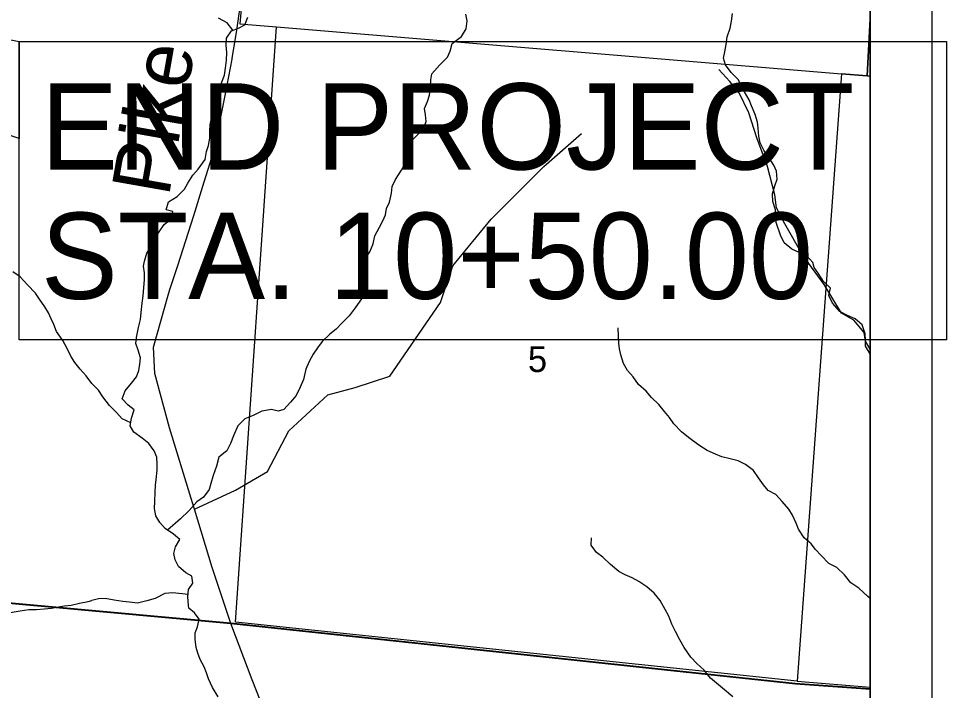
# Model space of a CAD drawing. Extents: x -13.1 to 43.1, y 0 to 22.
# Drawn here: x 7.517 to 9.024, y 15.746 to 16.837 of the extents above; entities that cross this region are included whole.
import ezdxf

# ---------------------------------------------------------------- set-up
doc = ezdxf.new("R2010")
doc.units = 0
for name, color, linetype in [('GM_X_Corporation', 7, 'Continuous'), ('GM_X_Minor_River', 7, 'Continuous'), ('GM_X_Minor_River_Text', 7, 'Continuous'), ('GM_X_Section_Text', 7, 'Continuous'), ('GM_X_State_Route', 7, 'Continuous'), ('GM_X_Township_Road', 7, 'Continuous'), ('SH_Data', 7, 'Continuous'), ('SH_Masking', 7, 'Continuous'), ('SH_Text', 7, 'Continuous')]:
    doc.layers.add(name, color=color, linetype=linetype)

msp = doc.modelspace()

# ---------------------------------------------------------------- linework, layer by layer
at = {"layer": 'GM_X_Corporation'}
for points in [[(8.9, 15.7487), (8.9, 20.9), (7.0804, 20.9), (7.0615, 20.6138), (7.0162, 19.896), (7.0106, 19.8452), (6.9616, 19.1692), (6.9507, 19.0184), (6.8365, 17.1257), (6.8234, 16.908), (6.7528, 15.9566), (7.8612, 15.855), (8.7782, 15.7572)], [(8.9, 15.7487), (8.9, 20.9), (7.0804, 20.9), (7.0615, 20.6138), (7.0162, 19.896), (7.0106, 19.8452), (6.9616, 19.1692), (6.9507, 19.0184), (6.8365, 17.1257), (6.8234, 16.908), (6.7528, 15.9566), (7.8612, 15.855), (8.7782, 15.7572)], [(8.9, 15.7481), (8.9, 20.9), (7.0807, 20.9), (7.0617, 20.6133), (7.0164, 19.8954), (7.0108, 19.8446), (6.9509, 19.0179), (6.8236, 16.9075), (6.7531, 15.956), (7.8614, 15.8545), (8.7784, 15.7567)], [(8.9, 16.8362), (8.9, 17.7183), (7.9639, 17.8036), (7.8759, 16.828), (7.9357, 16.8233), (8.8534, 16.7472), (8.8951, 16.7437)], [(8.9, 16.7433), (8.9, 16.8362), (8.8951, 16.7437)], [(7.9357, 16.8233), (8.8534, 16.7472), (8.7815, 15.7611), (7.8691, 15.8567)], [(8.9, 15.7513), (8.9, 16.7433), (8.8951, 16.7437), (8.8534, 16.7472), (8.7815, 15.7611)], [(6.619, 14.1), (8.9, 14.1), (8.9, 15.7487), (8.7782, 15.7572), (7.8612, 15.855), (6.7528, 15.9566), (6.6992, 15.2074)], [(6.619, 14.1), (8.9, 14.1), (8.9, 15.7487), (8.7782, 15.7572), (7.8612, 15.855), (6.7528, 15.9566), (6.6992, 15.2074)], [(6.6193, 14.1), (8.9, 14.1), (8.9, 15.7481), (8.7784, 15.7567), (7.8614, 15.8545), (6.7531, 15.956), (6.6994, 15.2069)]]:
    msp.add_lwpolyline(points, close=True, dxfattribs=at)
at = {"layer": 'GM_X_Minor_River'}
for p, q in [((7.8553, 16.8299), (7.8413, 16.8372)), ((8.2453, 16.8331), (8.2431, 16.8437)), ((8.6748, 16.8322), (8.6764, 16.8447)), ((7.8644, 16.8177), (7.8553, 16.8299)), ((8.2361, 16.8073), (8.2437, 16.8202)), ((8.2437, 16.8202), (8.2453, 16.8331)), ((8.6678, 16.8068), (8.6724, 16.8212)), ((8.6724, 16.8212), (8.6748, 16.8322)), ((8.2208, 16.7964), (8.2361, 16.8073)), ((8.6658, 16.7947), (8.6678, 16.8068)), ((8.2177, 16.7839), (8.2208, 16.7964)), ((8.6638, 16.7829), (8.6658, 16.7947)), ((8.2131, 16.7741), (8.2177, 16.7839)), ((8.6618, 16.7723), (8.6638, 16.7829)), ((8.1879, 16.7469), (8.2009, 16.7613)), ((8.2009, 16.7613), (8.2131, 16.7741)), ((8.6648, 16.7617), (8.6618, 16.7723)), ((8.6738, 16.7491), (8.6648, 16.7617)), ((8.1863, 16.7371), (8.1879, 16.7469)), ((8.6862, 16.7373), (8.6738, 16.7491)), ((8.1859, 16.7269), (8.1863, 16.7371)), ((8.6903, 16.7278), (8.6862, 16.7373)), ((8.1842, 16.7121), (8.1859, 16.7269)), ((8.6959, 16.7179), (8.6903, 16.7278)), ((8.7034, 16.7045), (8.6959, 16.7179)), ((8.1761, 16.6909), (8.1808, 16.7022)), ((8.1808, 16.7022), (8.1842, 16.7121)), ((8.7071, 16.695), (8.7034, 16.7045)), ((8.1776, 16.6803), (8.1761, 16.6909)), ((8.7131, 16.681), (8.7071, 16.695)), ((8.1748, 16.6594), (8.1786, 16.6696)), ((8.1786, 16.6696), (8.1776, 16.6803)), ((8.7171, 16.6684), (8.7131, 16.681)), ((8.1648, 16.6477), (8.1748, 16.6594)), ((8.7178, 16.6589), (8.7171, 16.6684)), ((8.7192, 16.646), (8.7178, 16.6589)), ((8.1553, 16.6387), (8.1648, 16.6477)), ((8.7214, 16.635), (8.7192, 16.646)), ((8.1491, 16.6163), (8.1507, 16.6266)), ((8.1507, 16.6266), (8.1553, 16.6387)), ((8.7274, 16.6221), (8.7214, 16.635)), ((8.1456, 16.6038), (8.1491, 16.6163)), ((8.7375, 16.608), (8.7274, 16.6221)), ((8.1387, 16.5906), (8.1456, 16.6038)), ((8.7435, 16.5985), (8.7375, 16.608)), ((8.7476, 16.5889), (8.7435, 16.5985)), ((8.1291, 16.5755), (8.1387, 16.5906)), ((8.749, 16.5757), (8.7476, 16.5889)), ((8.1233, 16.5638), (8.1291, 16.5755)), ((8.7413, 16.5522), (8.7452, 16.5654)), ((8.7452, 16.5654), (8.749, 16.5757)), ((8.119, 16.5388), (8.1221, 16.5532)), ((8.1221, 16.5532), (8.1233, 16.5638)), ((8.7416, 16.5397), (8.7413, 16.5522)), ((8.114, 16.5286), (8.119, 16.5388)), ((8.746, 16.526), (8.7416, 16.5397)), ((8.1124, 16.5183), (8.114, 16.5286)), ((8.7463, 16.515), (8.746, 16.526)), ((8.1028, 16.4979), (8.1085, 16.5085)), ((8.1085, 16.5085), (8.1124, 16.5183)), ((8.7474, 16.5055), (8.7463, 16.515)), ((8.754, 16.485), (8.7474, 16.5055)), ((8.0955, 16.4839), (8.1028, 16.4979)), ((8.0924, 16.4711), (8.0955, 16.4839)), ((8.76, 16.4728), (8.754, 16.485)), ((8.087, 16.4578), (8.0924, 16.4711)), ((8.7728, 16.4621), (8.76, 16.4728)), ((8.7845, 16.4567), (8.7728, 16.4621)), ((8.0762, 16.434), (8.0778, 16.4442)), ((8.0778, 16.4442), (8.087, 16.4578)), ((8.797, 16.4513), (8.7845, 16.4567)), ((8.8067, 16.4406), (8.797, 16.4513)), ((7.7212, 16.4237), (7.7195, 16.4347)), ((8.0762, 16.434), (8.0804, 16.4108)), ((8.809, 16.4325), (8.8067, 16.4406)), ((8.8153, 16.4234), (8.809, 16.4325)), ((7.5192, 16.4175), (7.5072, 16.4255)), ((7.5312, 16.4045), (7.5192, 16.4175)), ((7.7211, 16.4124), (7.7212, 16.4237)), ((8.8239, 16.4101), (8.8153, 16.4234)), ((7.544, 16.3908), (7.5312, 16.4045)), ((7.7191, 16.3866), (7.7199, 16.4002)), ((7.7199, 16.4002), (7.7211, 16.4124)), ((8.0804, 16.4108), (8.0796, 16.3968)), ((8.8352, 16.3991), (8.8239, 16.4101)), ((8.8325, 16.3869), (8.8352, 16.3991)), ((7.5504, 16.3812), (7.544, 16.3908)), ((7.7175, 16.3749), (7.7191, 16.3866)), ((8.0796, 16.3968), (8.0738, 16.3816)), ((8.8388, 16.3748), (8.8325, 16.3869)), ((7.559, 16.3687), (7.5504, 16.3812)), ((7.565, 16.3588), (7.559, 16.3687)), ((7.7159, 16.3593), (7.7175, 16.3749)), ((8.0738, 16.3816), (8.0635, 16.3673)), ((8.8505, 16.3614), (8.8388, 16.3748)), ((7.5694, 16.3493), (7.565, 16.3588)), ((7.7147, 16.348), (7.7159, 16.3593)), ((8.0536, 16.3541), (8.0418, 16.3424)), ((8.0635, 16.3673), (8.0536, 16.3541)), ((8.8633, 16.3549), (8.8505, 16.3614)), ((8.8754, 16.3491), (8.8633, 16.3549)), ((7.5736, 16.3398), (7.5694, 16.3493)), ((7.5784, 16.3284), (7.5736, 16.3398)), ((7.7112, 16.3351), (7.7147, 16.348)), ((8.0418, 16.3424), (8.0323, 16.3326)), ((8.887, 16.3396), (8.8754, 16.3491)), ((8.8919, 16.3248), (8.887, 16.3396)), ((7.5885, 16.3139), (7.5784, 16.3284)), ((7.7081, 16.3188), (7.7112, 16.3351)), ((8.022, 16.3244), (8.0098, 16.3123)), ((8.0323, 16.3326), (8.022, 16.3244)), ((8.4909, 16.3213), (8.4903, 16.3346)), ((8.8922, 16.3149), (8.8919, 16.3248)), ((7.596, 16.2998), (7.5885, 16.3139)), ((7.7072, 16.3093), (7.7081, 16.3188)), ((7.7109, 16.2983), (7.7072, 16.3093)), ((8.0098, 16.3123), (8.0022, 16.3021)), ((8.4916, 16.3099), (8.4909, 16.3213)), ((8.4927, 16.3005), (8.4916, 16.3099)), ((8.8921, 16.3047), (8.8922, 16.3149)), ((7.6016, 16.2888), (7.596, 16.2998)), ((7.7147, 16.2858), (7.7109, 16.2983)), ((8.0022, 16.3021), (7.9949, 16.2916)), ((8.4949, 16.2906), (8.4927, 16.3005)), ((8.8996, 16.2925), (8.8921, 16.3047)), ((7.608, 16.2785), (7.6016, 16.2888)), ((7.6166, 16.2675), (7.608, 16.2785)), ((7.7138, 16.2756), (7.7147, 16.2858)), ((7.9888, 16.2802), (7.9834, 16.2674)), ((7.9949, 16.2916), (7.9888, 16.2802)), ((8.4994, 16.2765), (8.4949, 16.2906)), ((8.9, 16.2922), (8.8996, 16.2925)), ((7.6263, 16.2568), (7.6166, 16.2675)), ((7.708, 16.2551), (7.7119, 16.2653)), ((7.7119, 16.2653), (7.7138, 16.2756)), ((7.9834, 16.2674), (7.9795, 16.2507)), ((8.5057, 16.2655), (8.4994, 16.2765)), ((8.5151, 16.2552), (8.5057, 16.2655)), ((7.6357, 16.2442), (7.6263, 16.2568)), ((7.7, 16.2446), (7.708, 16.2551)), ((7.9795, 16.2507), (7.9742, 16.2382)), ((8.5237, 16.2426), (8.5151, 16.2552)), ((7.6462, 16.2332), (7.6357, 16.2442)), ((7.6534, 16.2225), (7.6462, 16.2332)), ((7.6851, 16.2193), (7.6897, 16.2325)), ((7.6897, 16.2325), (7.7, 16.2446)), ((7.9742, 16.2382), (7.9673, 16.225)), ((8.5358, 16.2319), (8.5237, 16.2426)), ((7.6642, 16.2084), (7.6534, 16.2225)), ((7.6945, 16.209), (7.6851, 16.2193)), ((7.9673, 16.225), (7.9581, 16.2141)), ((8.5448, 16.2213), (8.5358, 16.2319)), ((8.5564, 16.2102), (8.5448, 16.2213)), ((7.6759, 16.1974), (7.6642, 16.2084)), ((7.7043, 16.2013), (7.6945, 16.209)), ((7.9581, 16.2141), (7.9475, 16.202)), ((8.5658, 16.1988), (8.5564, 16.2102)), ((7.6849, 16.1871), (7.6759, 16.1974)), ((7.6981, 16.1756), (7.7, 16.1877)), ((7.7, 16.1877), (7.7043, 16.2013)), ((7.8979, 16.1925), (7.8842, 16.1869)), ((7.9119, 16.1992), (7.8979, 16.1925)), ((7.9274, 16.2018), (7.9119, 16.1992)), ((7.938, 16.1994), (7.9274, 16.2018)), ((7.9475, 16.202), (7.938, 16.1994)), ((8.5737, 16.1889), (8.5658, 16.1988)), ((8.5808, 16.1786), (8.5737, 16.1889)), ((7.6988, 16.1804), (7.6849, 16.1871)), ((7.704, 16.1653), (7.6981, 16.1756)), ((7.8728, 16.1756), (7.8659, 16.1594)), ((7.8842, 16.1869), (7.8728, 16.1756)), ((8.5932, 16.1656), (8.5808, 16.1786)), ((7.7172, 16.1554), (7.704, 16.1653)), ((7.8659, 16.1594), (7.8609, 16.1469)), ((8.6049, 16.1564), (8.5932, 16.1656)), ((7.7281, 16.147), (7.7172, 16.1554)), ((7.7371, 16.1348), (7.7281, 16.147)), ((7.8609, 16.1469), (7.8548, 16.1352)), ((8.6214, 16.1442), (8.6049, 16.1564)), ((8.635, 16.1354), (8.6214, 16.1442)), ((7.7412, 16.1245), (7.7371, 16.1348)), ((7.8548, 16.1352), (7.8418, 16.1246)), ((8.6486, 16.1296), (8.635, 16.1354)), ((8.6587, 16.125), (8.6486, 16.1296)), ((7.7419, 16.1135), (7.7412, 16.1245)), ((7.7419, 16.1037), (7.7419, 16.1135)), ((7.8418, 16.1246), (7.838, 16.1099)), ((8.6727, 16.1219), (8.6587, 16.125)), ((8.6856, 16.1188), (8.6727, 16.1219)), ((8.6976, 16.1126), (8.6856, 16.1188)), ((8.7104, 16.1031), (8.6976, 16.1126)), ((7.7399, 16.0885), (7.7419, 16.1037)), ((7.838, 16.1099), (7.8329, 16.0948)), ((8.7187, 16.0913), (8.7104, 16.1031)), ((7.739, 16.0791), (7.7399, 16.0885)), ((7.8291, 16.0819), (7.826, 16.0721)), ((7.8329, 16.0948), (7.8291, 16.0819)), ((8.7265, 16.0798), (8.7187, 16.0913)), ((7.7377, 16.0525), (7.7382, 16.0677)), ((7.7382, 16.0677), (7.739, 16.0791)), ((7.826, 16.0721), (7.8172, 16.0596)), ((8.7344, 16.0703), (8.7265, 16.0798)), ((8.7468, 16.0642), (8.7344, 16.0703)), ((7.7373, 16.0412), (7.7377, 16.0525)), ((7.8062, 16.0521), (7.7932, 16.0374)), ((7.8172, 16.0596), (7.8062, 16.0521)), ((8.757, 16.0527), (8.7468, 16.0642)), ((8.7675, 16.0405), (8.757, 16.0527)), ((7.7395, 16.0294), (7.7373, 16.0412)), ((7.7932, 16.0374), (7.7795, 16.0246)), ((8.7735, 16.0306), (8.7675, 16.0405)), ((7.7458, 16.0184), (7.7395, 16.0294)), ((7.7795, 16.0246), (7.7586, 16.0063)), ((8.7795, 16.0173), (8.7735, 16.0306)), ((7.7549, 16.0088), (7.7458, 16.0184)), ((7.7684, 15.9997), (7.7549, 16.0088)), ((8.7832, 16.0078), (8.7795, 16.0173)), ((8.7925, 15.9938), (8.7832, 16.0078)), ((7.7786, 15.9912), (7.7684, 15.9997)), ((7.7713, 15.9792), (7.7786, 15.9912)), ((8.4468, 15.982), (8.4472, 15.9937)), ((8.8038, 15.9842), (8.7925, 15.9938)), ((7.769, 15.9682), (7.7713, 15.9792)), ((8.4554, 15.9698), (8.4468, 15.982)), ((8.8113, 15.9747), (8.8038, 15.9842)), ((7.7708, 15.9579), (7.769, 15.9682)), ((8.4656, 15.9625), (8.4554, 15.9698)), ((8.478, 15.9503), (8.4656, 15.9625)), ((8.82, 15.9648), (8.8113, 15.9747)), ((8.8327, 15.9518), (8.82, 15.9648)), ((7.7764, 15.9469), (7.7708, 15.9579)), ((7.7881, 15.937), (7.7764, 15.9469)), ((8.4915, 15.9392), (8.478, 15.9503)), ((8.8459, 15.9457), (8.8327, 15.9518)), ((7.7979, 15.9316), (7.7881, 15.937)), ((7.7997, 15.9199), (7.7979, 15.9316)), ((8.5017, 15.9339), (8.4915, 15.9392)), ((8.513, 15.9289), (8.5017, 15.9339)), ((8.858, 15.9334), (8.8459, 15.9457)), ((8.8685, 15.9209), (8.858, 15.9334)), ((7.7928, 15.9097), (7.7997, 15.9199)), ((8.5243, 15.9227), (8.513, 15.9289)), ((8.5371, 15.9139), (8.5243, 15.9227)), ((8.8813, 15.9121), (8.8685, 15.9209)), ((7.7542, 15.9031), (7.7386, 15.8952)), ((7.7674, 15.9045), (7.7542, 15.9031)), ((7.792, 15.9018), (7.7674, 15.9045)), ((7.7916, 15.8979), (7.7928, 15.9097)), ((8.5492, 15.904), (8.5371, 15.9139)), ((8.5585, 15.8918), (8.5492, 15.904)), ((8.8963, 15.8987), (8.8813, 15.9121)), ((7.6463, 15.8947), (7.6354, 15.8921)), ((7.6573, 15.895), (7.6463, 15.8947)), ((7.6717, 15.8923), (7.6573, 15.895)), ((7.686, 15.8906), (7.6717, 15.8923)), ((7.697, 15.8891), (7.686, 15.8906)), ((7.7095, 15.8878), (7.697, 15.8891)), ((7.725, 15.8912), (7.7095, 15.8878)), ((7.7386, 15.8952), (7.725, 15.8912)), ((7.7926, 15.8839), (7.7916, 15.8979)), ((8.5671, 15.8773), (8.5585, 15.8918)), ((8.9, 15.8953), (8.8963, 15.8987)), ((7.7934, 15.8796), (7.7926, 15.8839)), ((8.5728, 15.8667), (8.5671, 15.8773)), ((8.5776, 15.8534), (8.5728, 15.8667)), ((8.5839, 15.8416), (8.5776, 15.8534)), ((8.5907, 15.8283), (8.5839, 15.8416)), ((8.5975, 15.8155), (8.5907, 15.8283))]:
    msp.add_line(p, q, dxfattribs=at)
for points in [[(7.7195, 16.4347), (7.7214, 16.4431), (7.7249, 16.4556), (7.7326, 16.4673), (7.7387, 16.4806), (7.7449, 16.4904), (7.7533, 16.5021), (7.7647, 16.5115), (7.7674, 16.5236), (7.7561, 16.5263), (7.76, 16.5392), (7.7744, 16.5478), (7.7859, 16.5595), (7.7916, 16.5697), (7.7997, 16.5826), (7.8085, 16.5924), (7.8196, 16.6079), (7.8219, 16.6207), (7.825, 16.6306), (7.827, 16.6427), (7.8275, 16.6541), (7.8279, 16.6643), (7.8307, 16.6776), (7.833, 16.6878), (7.8373, 16.6988), (7.8411, 16.7097), (7.8439, 16.72), (7.8462, 16.7321), (7.8512, 16.7446), (7.8528, 16.7563), (7.8541, 16.7692), (7.8549, 16.7817), (7.8539, 16.7935), (7.8543, 16.8049), (7.8624, 16.817), (7.8737, 16.8211), (7.884, 16.8263), (7.889, 16.8388)], [(7.5031, 15.8727), (7.519, 15.8754), (7.533, 15.8773), (7.5455, 15.8776), (7.558, 15.8784), (7.5701, 15.8795), (7.5814, 15.8818), (7.5913, 15.8833), (7.6019, 15.8844), (7.6155, 15.8878), (7.6295, 15.8905), (7.6356, 15.8922)], [(7.841, 15.7356), (7.8315, 15.7508), (7.8251, 15.7648), (7.8221, 15.7743), (7.8179, 15.7842), (7.8115, 15.7963), (7.8077, 15.8062), (7.8051, 15.8156), (7.8032, 15.8293), (7.8032, 15.8395), (7.8074, 15.849), (7.81, 15.8615), (7.8021, 15.8721), (7.7934, 15.8796)], [(8.6766, 15.7358), (8.6633, 15.7472), (8.6535, 15.7548), (8.6403, 15.7661), (8.63, 15.779), (8.6183, 15.7897), (8.6085, 15.7999), (8.5975, 15.8155)]]:
    msp.add_lwpolyline(points, dxfattribs=at)
at = {"layer": 'GM_X_State_Route'}
for points in [[(7.8635, 16.7717), (7.871, 16.818), (7.8791, 16.8748), (7.8872, 16.9309), (7.8916, 16.9589), (7.9025, 16.9948), (7.9138, 17.022), (7.9354, 17.0655), (7.9597, 17.1142), (7.9666, 17.1289), (7.9702, 17.1463), (7.9745, 17.1982), (7.9783, 17.2494), (7.9838, 17.3062), (7.9884, 17.3517), (7.9935, 17.3763), (8.0037, 17.4107), (8.0227, 17.4629), (8.0421, 17.5147), (8.0483, 17.5306)], [(7.8614, 15.8545), (7.8311, 15.9454), (7.8023, 16.0401), (7.7971, 16.0573), (7.7617, 16.1722), (7.738, 16.2605), (7.736, 16.3033), (7.7594, 16.3876), (7.7624, 16.397), (7.7751, 16.4358), (7.8012, 16.5171), (7.818, 16.5716), (7.8336, 16.6215), (7.8387, 16.6442), (7.8526, 16.7146), (7.8634, 16.7707), (7.8635, 16.7717)], [(8.1369, 14.8166), (8.1591, 14.8691), (8.1634, 14.884), (8.1663, 14.9105), (8.1666, 14.942), (8.1654, 15.0225), (8.1645, 15.1105), (8.1627, 15.155), (8.1589, 15.1867), (8.152, 15.2168), (8.1215, 15.2866), (8.1082, 15.3148), (8.063, 15.4115), (8.0483, 15.4421), (8.0087, 15.5276), (7.9686, 15.5952), (7.9313, 15.674), (7.8962, 15.7631), (7.8614, 15.8545)]]:
    msp.add_lwpolyline(points, dxfattribs=at)
at = {"layer": 'GM_X_Township_Road'}
for points in [[(8.9, 16.3001), (8.8923, 16.3131), (8.8903, 16.3268), (8.8734, 16.3468), (8.8532, 16.3584), (8.8251, 16.4049), (8.7898, 16.4532), (8.7614, 16.5035), (8.7479, 16.5293), (8.7451, 16.5505), (8.733, 16.5964), (8.7159, 16.6433), (8.7027, 16.6835), (8.6869, 16.716), (8.672, 16.7345), (8.654, 16.7538)], [(7.8023, 16.0401), (7.8692, 16.0712), (7.9207, 16.1016), (7.9558, 16.1672), (8.019, 16.2258), (8.0635, 16.2375), (8.1197, 16.2562), (8.2017, 16.3757), (8.2221, 16.4351), (8.2841, 16.5112), (8.3696, 16.5965), (8.431, 16.6499)]]:
    msp.add_lwpolyline(points, dxfattribs=at)
at = {"layer": 'SH_Data'}
for p, q in [((9, 21), (9, 14)), ((8.9, 20.9), (8.9, 14.1))]:
    msp.add_line(p, q, dxfattribs=at)
at = {"layer": 'SH_Masking'}
msp.add_lwpolyline([(7.5178, 16.7996), (9.0237, 16.7996), (9.0237, 16.3151), (7.5178, 16.3151)], close=True, dxfattribs=at)
at = {"layer": 'SH_Text'}
for points in [[(7.5178, 16.6422), (6.3758, 17.0288), (7.5178, 16.7996)], [(7.5178, 16.7996), (9.0237, 16.7996), (9.0237, 16.3151), (7.5178, 16.3151)]]:
    msp.add_lwpolyline(points, close=True, dxfattribs=at)

# ---------------------------------------------------------------- texts
at = {"layer": 'GM_X_Minor_River_Text'}
msp.add_text('Pike', height=0.0947, rotation=79.9999, dxfattribs=at).set_placement((7.7605, 16.5459))
at = {"layer": 'GM_X_Section_Text'}
msp.add_text('5', height=0.0419, rotation=0, dxfattribs=at).set_placement((8.3439, 16.2629))
at = {"layer": 'SH_Text'}
for s, p in [('END PROJECT', (7.5529, 16.5916)), ('STA. 10+50.00', (7.5529, 16.3816))]:
    msp.add_text(s, height=0.14, dxfattribs=at).set_placement(p)

doc.saveas('drawing.dxf')
